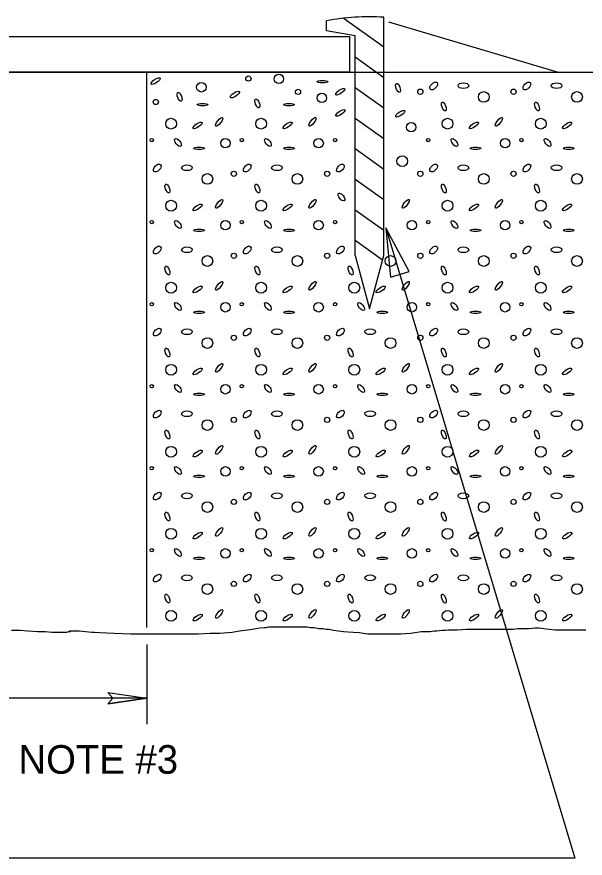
# Model space of a CAD drawing. Extents: x 12.5 to 19.6, y 6 to 16.
# Drawn here: x 16.462 to 17.653, y 11.231 to 12.995 of the extents above; entities that cross this region are included whole.
import ezdxf

# ---------------------------------------------------------------- set-up
doc = ezdxf.new("R2010")
doc.units = 0
for name, color, linetype in [('Default', 7, 'Continuous'), ('DETL-DIMS', 7, 'Continuous'), ('DETL-NOTE', 7, 'Continuous'), ('PVMT-FILL', 7, 'Continuous'), ('ROAD-EDGE', 7, 'Continuous'), ('SECT-SUBP_P', 7, 'Continuous')]:
    doc.layers.add(name, color=color, linetype=linetype)

msp = doc.modelspace()

# ---------------------------------------------------------------- linework, layer by layer
at = {"layer": 'Default'}
for p, q in [((17.1109, 12.9663), (17.1109, 12.9867)), ((17.2309, 12.9314), (17.1462, 12.9919)), ((17.2309, 12.4949), (17.2309, 12.994)), ((17.2409, 12.9844), (17.5967, 12.8792)), ((17.1109, 12.9663), (17.1709, 12.9557)), ((17.1709, 12.4949), (17.1709, 12.9557)), ((17.2309, 12.8673), (17.1709, 12.9102)), ((17.2309, 12.8033), (17.1709, 12.8461)), ((17.2309, 12.7392), (17.1709, 12.7821)), ((17.2309, 12.6752), (17.1709, 12.718)), ((17.2309, 12.6111), (17.1709, 12.654)), ((17.2309, 12.547), (17.1709, 12.5899)), ((17.2282, 12.4849), (17.1709, 12.5259)), ((17.1709, 12.4949), (17.2009, 12.3829)), ((17.2009, 12.3829), (17.2309, 12.4949))]:
    msp.add_line(p, q, dxfattribs=at)
msp.add_arc((17.2009, 12.4949), 0.5, 86.5602, 100.3698, dxfattribs=at)
at = {"layer": 'DETL-DIMS'}
for p, q in [((16.653, 11.5784), (16.7348, 11.5665)), ((16.653, 11.5784), (16.6632, 11.5665)), ((16.7348, 11.5665), (15.0348, 11.5665)), ((16.653, 11.5546), (16.7348, 11.5665)), ((16.653, 11.5546), (16.6632, 11.5665))]:
    msp.add_line(p, q, dxfattribs=at)
msp.add_lwpolyline([(17.2355, 12.5529), (17.6317, 11.2314), (16.1411, 11.2314)], dxfattribs=at)
for points in [[(17.2843, 12.4611), (17.2355, 12.5529), (17.2452, 12.4493)], [(16.653, 11.5784), (16.7348, 11.5665), (16.653, 11.5546), (16.6632, 11.5665)]]:
    msp.add_lwpolyline(points, close=True, dxfattribs=at)
at = {"layer": 'PVMT-FILL'}
for points in [[(16.4509, 11.7091), (16.463, 11.7091), (16.469, 11.7091), (16.4848, 11.7079), (16.5053, 11.7067), (16.5223, 11.7067), (16.5356, 11.7055), (16.5416, 11.7055), (16.5477, 11.7055), (16.5501, 11.7055), (16.5525, 11.7055), (16.5549, 11.7055), (16.5561, 11.7055), (16.5586, 11.7055), (16.5646, 11.7055), (16.567, 11.7055), (16.5707, 11.7067), (16.5719, 11.7067), (16.5731, 11.7067), (16.5743, 11.7067), (16.5731, 11.7067), (16.5719, 11.7067), (16.5731, 11.7079), (16.5743, 11.7079), (16.5755, 11.7079), (16.5767, 11.7079), (16.5791, 11.7079), (16.5924, 11.7079), (16.619, 11.7055), (16.6251, 11.7055), (16.636, 11.7043), (16.6662, 11.7031), (16.7001, 11.7018), (16.7231, 11.7018), (16.7533, 11.7018), (16.7836, 11.7018), (16.8198, 11.7018), (16.8307, 11.7018), (16.8428, 11.7018), (16.867, 11.7031), (16.8876, 11.7031), (16.9045, 11.7043), (16.913, 11.7055), (16.9287, 11.7079), (16.9456, 11.7103), (16.9553, 11.7115), (16.9626, 11.7127), (16.971, 11.7139), (16.9807, 11.7152), (16.9844, 11.7152), (16.9892, 11.7164), (16.9952, 11.7164), (17.0049, 11.7164), (17.0085, 11.7164), (17.0134, 11.7164), (17.0219, 11.7164), (17.0255, 11.7164), (17.0327, 11.7164), (17.0424, 11.7164), (17.0594, 11.7164), (17.0702, 11.7164), (17.0775, 11.7152), (17.0848, 11.7152), (17.0956, 11.7127), (17.1041, 11.7127), (17.1102, 11.7115), (17.1162, 11.7115), (17.1259, 11.7091), (17.1464, 11.7067), (17.167, 11.7055), (17.1803, 11.7043), (17.1876, 11.7031), (17.1973, 11.7018), (17.2057, 11.7018), (17.219, 11.7018), (17.2287, 11.7018), (17.2481, 11.7018), (17.2662, 11.7018), (17.2868, 11.7031), (17.3097, 11.7067), (17.3182, 11.7067), (17.3279, 11.7067), (17.3364, 11.7079), (17.3424, 11.7079), (17.3533, 11.7091), (17.3593, 11.7091), (17.3666, 11.7103), (17.3775, 11.7103), (17.3847, 11.7103), (17.4041, 11.7115), (17.4235, 11.7115), (17.4295, 11.7115), (17.4368, 11.7115), (17.4428, 11.7115), (17.4489, 11.7115), (17.4525, 11.7115), (17.4537, 11.7115), (17.4561, 11.7115), (17.4573, 11.7115), (17.4622, 11.7115), (17.467, 11.7115), (17.4718, 11.7115), (17.4791, 11.7115), (17.4827, 11.7115), (17.4851, 11.7115), (17.4876, 11.7115), (17.4948, 11.7115), (17.5021, 11.7115), (17.5118, 11.7127), (17.5275, 11.7127), (17.536, 11.7127), (17.5481, 11.7139), (17.5529, 11.7139)], [(17.5529, 11.7139), (17.5565, 11.7139), (17.5662, 11.7127), (17.5904, 11.7103), (17.617, 11.7103), (17.6291, 11.7103), (17.6388, 11.7103), (17.6545, 11.7103)]]:
    msp.add_lwpolyline(points, dxfattribs=at)
for centre, radius in [((17.0112, 12.8648), 0.0099), ((16.8487, 12.8472), 0.0099), ((16.9473, 12.8656), 0.00546), ((17.0513, 12.8375), 0.00546), ((17.3076, 12.8379), 0.00546), ((17.4405, 12.827), 0.0112), ((17.5029, 12.8379), 0.00546), ((17.6359, 12.827), 0.0112), ((16.7532, 12.8165), 0.00546), ((17.1013, 12.825), 0.0099), ((16.7853, 12.7709), 0.0113), ((16.9739, 12.7709), 0.0113), ((17.2886, 12.7634), 0.0099), ((17.3646, 12.7709), 0.0113), ((17.5599, 12.7709), 0.0113), ((16.7449, 12.7365), 0.00349), ((16.8992, 12.7299), 0.0099), ((16.9334, 12.7365), 0.00349), ((17.0945, 12.7299), 0.0099), ((17.1288, 12.7365), 0.00349), ((17.3241, 12.7365), 0.00349), ((17.4852, 12.7299), 0.0099), ((17.5194, 12.7365), 0.00349), ((17.2697, 12.6924), 0.0113), ((16.8613, 12.6551), 0.0112), ((16.9169, 12.666), 0.00546), ((17.0499, 12.6551), 0.0112), ((17.1123, 12.666), 0.00546), ((17.3076, 12.666), 0.00546), ((17.4405, 12.6551), 0.0112), ((17.5029, 12.666), 0.00546), ((17.6359, 12.6551), 0.0112), ((16.7853, 12.599), 0.0113), ((16.9739, 12.599), 0.0113), ((17.3646, 12.599), 0.0113), ((17.5599, 12.599), 0.0113), ((16.7449, 12.5646), 0.00349), ((16.8992, 12.558), 0.0099), ((16.9334, 12.5646), 0.00349), ((17.0945, 12.558), 0.0099), ((17.1288, 12.5646), 0.00349), ((17.2898, 12.558), 0.0099), ((17.3241, 12.5646), 0.00349), ((17.4852, 12.558), 0.0099), ((17.5194, 12.5646), 0.00349), ((16.8613, 12.4831), 0.0112), ((16.9169, 12.4941), 0.00546), ((17.0499, 12.4831), 0.0112), ((17.1123, 12.4941), 0.00546), ((17.2452, 12.4831), 0.0112), ((17.3076, 12.4941), 0.00546), ((17.4405, 12.4831), 0.0112), ((17.5029, 12.4941), 0.00546), ((17.6359, 12.4831), 0.0112), ((16.7853, 12.4271), 0.0113), ((16.9739, 12.4271), 0.0113), ((17.1692, 12.4271), 0.0113), ((17.3646, 12.4271), 0.0113), ((17.5599, 12.4271), 0.0113), ((16.7449, 12.3926), 0.00349), ((16.8992, 12.3861), 0.0099), ((16.9334, 12.3926), 0.00349), ((17.0945, 12.3861), 0.0099), ((17.1288, 12.3926), 0.00349), ((17.2898, 12.3861), 0.0099), ((17.3241, 12.3926), 0.00349), ((17.4852, 12.3861), 0.0099), ((17.5194, 12.3926), 0.00349), ((16.9169, 12.3221), 0.00546), ((17.1123, 12.3221), 0.00546), ((17.3076, 12.3221), 0.00546), ((17.5029, 12.3221), 0.00546), ((16.8613, 12.3112), 0.0112), ((17.0499, 12.3112), 0.0112), ((17.2452, 12.3112), 0.0112), ((17.4405, 12.3112), 0.0112), ((17.6359, 12.3112), 0.0112), ((16.7853, 12.2552), 0.0113), ((16.9739, 12.2552), 0.0113), ((17.1692, 12.2552), 0.0113), ((17.3646, 12.2552), 0.0113), ((17.5599, 12.2552), 0.0113), ((16.7449, 12.2207), 0.00349), ((16.8992, 12.2142), 0.0099), ((16.9334, 12.2207), 0.00349), ((17.0945, 12.2142), 0.0099), ((17.1288, 12.2207), 0.00349), ((17.2898, 12.2142), 0.0099), ((17.3241, 12.2207), 0.00349), ((17.4852, 12.2142), 0.0099), ((17.5194, 12.2207), 0.00349), ((16.8613, 12.1393), 0.0112), ((16.9169, 12.1502), 0.00546), ((17.0499, 12.1393), 0.0112), ((17.1123, 12.1502), 0.00546), ((17.2452, 12.1393), 0.0112), ((17.3076, 12.1502), 0.00546), ((17.4405, 12.1393), 0.0112), ((17.5029, 12.1502), 0.00546), ((17.6359, 12.1393), 0.0112), ((16.7853, 12.0833), 0.0113), ((16.9739, 12.0833), 0.0113), ((17.1692, 12.0833), 0.0113), ((17.3646, 12.0833), 0.0113), ((17.5599, 12.0833), 0.0113), ((16.7449, 12.0488), 0.00349), ((16.8992, 12.0422), 0.0099), ((16.9334, 12.0488), 0.00349), ((17.0945, 12.0422), 0.0099), ((17.1288, 12.0488), 0.00349), ((17.2898, 12.0422), 0.0099), ((17.3241, 12.0488), 0.00349), ((17.4852, 12.0422), 0.0099), ((17.5194, 12.0488), 0.00349), ((16.8613, 11.9674), 0.0112), ((16.9169, 11.9783), 0.00546), ((17.0499, 11.9674), 0.0112), ((17.1123, 11.9783), 0.00546), ((17.2452, 11.9674), 0.0112), ((17.3076, 11.9783), 0.00546), ((17.4405, 11.9674), 0.0112), ((17.5029, 11.9783), 0.00546), ((17.6359, 11.9674), 0.0112), ((16.7853, 11.9114), 0.0113), ((16.9739, 11.9114), 0.0113), ((17.1692, 11.9114), 0.0113), ((17.3646, 11.9114), 0.0113), ((17.5599, 11.9114), 0.0113), ((16.7449, 11.8769), 0.00349), ((16.8992, 11.8703), 0.0099), ((16.9334, 11.8769), 0.00349), ((17.0945, 11.8703), 0.0099), ((17.1288, 11.8769), 0.00349), ((17.2898, 11.8703), 0.0099), ((17.3241, 11.8769), 0.00349), ((17.4852, 11.8703), 0.0099), ((17.5194, 11.8769), 0.00349), ((16.8613, 11.7955), 0.0112), ((16.9169, 11.8064), 0.00546), ((17.0499, 11.7955), 0.0112), ((17.1123, 11.8064), 0.00546), ((17.2452, 11.7955), 0.0112), ((17.3076, 11.8064), 0.00546), ((17.4405, 11.7955), 0.0112), ((17.5029, 11.8064), 0.00546), ((17.6359, 11.7955), 0.0112), ((16.7853, 11.7394), 0.0113), ((16.9739, 11.7394), 0.0113), ((17.1692, 11.7394), 0.0113), ((17.3646, 11.7394), 0.0113), ((17.5599, 11.7394), 0.0113)]:
    msp.add_circle(centre, radius, dxfattribs=at)
for centre, major_axis, ratio in [((16.7529, 12.8601), (-0.00937, -0.00627), 0.338582), ((17.1024, 12.8589), (-0.0112, 0), 0.226521), ((17.2608, 12.8459), (-0.00349, 0.00926), 0.407015), ((17.3356, 12.8499), (0.007, 0.007), 0.581564), ((17.3978, 12.8506), (-0.0112, 0), 0.539468), ((17.5309, 12.8499), (0.007, 0.007), 0.581564), ((17.5931, 12.8506), (-0.0112, 0), 0.539468), ((16.9189, 12.832), (-0.00937, -0.00627), 0.338582), ((17.1398, 12.8379), (-0.00937, -0.00627), 0.338582), ((16.8031, 12.8273), (-0.00349, 0.00926), 0.407015), ((16.9661, 12.8133), (-0.00349, 0.00926), 0.407015), ((16.8511, 12.811), (-0.0112, 0), 0.226521), ((17.0325, 12.811), (-0.0112, 0), 0.226521), ((17.3568, 12.8069), (-0.00349, 0.00926), 0.407015), ((17.5521, 12.8069), (-0.00349, 0.00926), 0.407015), ((16.8862, 12.7749), (0.00695, 0.00888), 0.334091), ((17.0815, 12.7749), (0.00695, 0.00888), 0.334091), ((17.1398, 12.7934), (-0.00937, -0.00627), 0.338582), ((17.2654, 12.7917), (-0.00937, -0.00627), 0.338582), ((17.4722, 12.7749), (0.00695, 0.00888), 0.334091), ((16.8408, 12.7673), (-0.00937, -0.00627), 0.338582), ((17.0294, 12.7673), (-0.00937, -0.00627), 0.338582), ((17.42, 12.7673), (-0.00937, -0.00627), 0.338582), ((17.6153, 12.7673), (-0.00937, -0.00627), 0.338582), ((16.7997, 12.7315), (0.00613, -0.00777), 0.467307), ((16.9883, 12.7315), (0.00613, -0.00777), 0.467307), ((17.379, 12.7315), (0.00613, -0.00777), 0.467307), ((17.5743, 12.7315), (0.00613, -0.00777), 0.467307), ((16.844, 12.7195), (-0.0112, 0), 0.226521), ((17.0325, 12.7195), (-0.0112, 0), 0.226521), ((17.4232, 12.7195), (-0.0112, 0), 0.226521), ((17.6185, 12.7195), (-0.0112, 0), 0.226521), ((16.7563, 12.678), (0.007, 0.007), 0.581564), ((16.8185, 12.6786), (-0.0112, 0), 0.539468), ((16.9449, 12.678), (0.007, 0.007), 0.581564), ((17.0071, 12.6786), (-0.0112, 0), 0.539468), ((17.1402, 12.678), (0.007, 0.007), 0.581564), ((17.3356, 12.678), (0.007, 0.007), 0.581564), ((17.3978, 12.6786), (-0.0112, 0), 0.539468), ((17.5309, 12.678), (0.007, 0.007), 0.581564), ((17.5931, 12.6786), (-0.0112, 0), 0.539468), ((16.7775, 12.635), (-0.00349, 0.00926), 0.407015), ((16.9661, 12.635), (-0.00349, 0.00926), 0.407015), ((17.3568, 12.635), (-0.00349, 0.00926), 0.407015), ((17.5521, 12.635), (-0.00349, 0.00926), 0.407015), ((17.1422, 12.6172), (0.00613, -0.00777), 0.467307), ((16.8862, 12.603), (0.00695, 0.00888), 0.334091), ((17.0815, 12.603), (0.00695, 0.00888), 0.334091), ((17.2769, 12.603), (0.00695, 0.00888), 0.334091), ((17.4722, 12.603), (0.00695, 0.00888), 0.334091), ((16.8408, 12.5954), (-0.00937, -0.00627), 0.338582), ((17.0294, 12.5954), (-0.00937, -0.00627), 0.338582), ((17.42, 12.5954), (-0.00937, -0.00627), 0.338582), ((17.6153, 12.5954), (-0.00937, -0.00627), 0.338582), ((16.7997, 12.5596), (0.00613, -0.00777), 0.467307), ((16.9883, 12.5596), (0.00613, -0.00777), 0.467307), ((17.379, 12.5596), (0.00613, -0.00777), 0.467307), ((17.5743, 12.5596), (0.00613, -0.00777), 0.467307), ((16.844, 12.5476), (-0.0112, 0), 0.226521), ((17.0325, 12.5476), (-0.0112, 0), 0.226521), ((17.4232, 12.5476), (-0.0112, 0), 0.226521), ((17.6185, 12.5476), (-0.0112, 0), 0.226521), ((16.7563, 12.5061), (0.007, 0.007), 0.581564), ((16.8185, 12.5067), (-0.0112, 0), 0.539468), ((16.9449, 12.5061), (0.007, 0.007), 0.581564), ((17.0071, 12.5067), (-0.0112, 0), 0.539468), ((17.1402, 12.5061), (0.007, 0.007), 0.581564), ((17.3356, 12.5061), (0.007, 0.007), 0.581564), ((17.3978, 12.5067), (-0.0112, 0), 0.539468), ((17.5309, 12.5061), (0.007, 0.007), 0.581564), ((17.5931, 12.5067), (-0.0112, 0), 0.539468), ((16.7775, 12.4631), (-0.00349, 0.00926), 0.407015), ((16.9661, 12.4631), (-0.00349, 0.00926), 0.407015), ((17.1614, 12.4631), (-0.00349, 0.00926), 0.407015), ((17.3568, 12.4631), (-0.00349, 0.00926), 0.407015), ((17.5521, 12.4631), (-0.00349, 0.00926), 0.407015), ((16.8862, 12.4311), (0.00695, 0.00888), 0.334091), ((17.0815, 12.4311), (0.00695, 0.00888), 0.334091), ((17.2769, 12.4311), (0.00695, 0.00888), 0.334091), ((17.4722, 12.4311), (0.00695, 0.00888), 0.334091), ((16.8408, 12.4235), (-0.00937, -0.00627), 0.338582), ((17.0294, 12.4235), (-0.00937, -0.00627), 0.338582), ((17.2247, 12.4235), (-0.00937, -0.00627), 0.338582), ((17.42, 12.4235), (-0.00937, -0.00627), 0.338582), ((17.6153, 12.4235), (-0.00937, -0.00627), 0.338582), ((16.7997, 12.3876), (0.00613, -0.00777), 0.467307), ((16.9883, 12.3876), (0.00613, -0.00777), 0.467307), ((17.1836, 12.3876), (0.00613, -0.00777), 0.467307), ((17.379, 12.3876), (0.00613, -0.00777), 0.467307), ((17.5743, 12.3876), (0.00613, -0.00777), 0.467307), ((16.844, 12.3757), (-0.0112, 0), 0.226521), ((17.0325, 12.3757), (-0.0112, 0), 0.226521), ((17.2279, 12.3757), (-0.0112, 0), 0.226521), ((17.4232, 12.3757), (-0.0112, 0), 0.226521), ((17.6185, 12.3757), (-0.0112, 0), 0.226521), ((16.7563, 12.3341), (0.007, 0.007), 0.581564), ((16.8185, 12.3348), (-0.0112, 0), 0.539468), ((16.9449, 12.3341), (0.007, 0.007), 0.581564), ((17.0071, 12.3348), (-0.0112, 0), 0.539468), ((17.1402, 12.3341), (0.007, 0.007), 0.581564), ((17.2024, 12.3348), (-0.0112, 0), 0.539468), ((17.3356, 12.3341), (0.007, 0.007), 0.581564), ((17.3978, 12.3348), (-0.0112, 0), 0.539468), ((17.5309, 12.3341), (0.007, 0.007), 0.581564), ((17.5931, 12.3348), (-0.0112, 0), 0.539468), ((16.7775, 12.2912), (-0.00349, 0.00926), 0.407015), ((16.9661, 12.2912), (-0.00349, 0.00926), 0.407015), ((17.1614, 12.2912), (-0.00349, 0.00926), 0.407015), ((17.3568, 12.2912), (-0.00349, 0.00926), 0.407015), ((17.5521, 12.2912), (-0.00349, 0.00926), 0.407015), ((16.8408, 12.2516), (-0.00937, -0.00627), 0.338582), ((16.8862, 12.2592), (0.00695, 0.00888), 0.334091), ((17.0294, 12.2516), (-0.00937, -0.00627), 0.338582), ((17.0815, 12.2592), (0.00695, 0.00888), 0.334091), ((17.2247, 12.2516), (-0.00937, -0.00627), 0.338582), ((17.2769, 12.2592), (0.00695, 0.00888), 0.334091), ((17.42, 12.2516), (-0.00937, -0.00627), 0.338582), ((17.4722, 12.2592), (0.00695, 0.00888), 0.334091), ((17.6153, 12.2516), (-0.00937, -0.00627), 0.338582), ((16.7997, 12.2157), (0.00613, -0.00777), 0.467307), ((16.9883, 12.2157), (0.00613, -0.00777), 0.467307), ((17.1836, 12.2157), (0.00613, -0.00777), 0.467307), ((17.379, 12.2157), (0.00613, -0.00777), 0.467307), ((17.5743, 12.2157), (0.00613, -0.00777), 0.467307), ((16.844, 12.2038), (-0.0112, 0), 0.226521), ((17.0325, 12.2038), (-0.0112, 0), 0.226521), ((17.2279, 12.2038), (-0.0112, 0), 0.226521), ((17.4232, 12.2038), (-0.0112, 0), 0.226521), ((17.6185, 12.2038), (-0.0112, 0), 0.226521), ((16.7563, 12.1622), (0.007, 0.007), 0.581564), ((16.8185, 12.1629), (-0.0112, 0), 0.539468), ((16.9449, 12.1622), (0.007, 0.007), 0.581564), ((17.0071, 12.1629), (-0.0112, 0), 0.539468), ((17.1402, 12.1622), (0.007, 0.007), 0.581564), ((17.2024, 12.1629), (-0.0112, 0), 0.539468), ((17.3356, 12.1622), (0.007, 0.007), 0.581564), ((17.3978, 12.1629), (-0.0112, 0), 0.539468), ((17.5309, 12.1622), (0.007, 0.007), 0.581564), ((17.5931, 12.1629), (-0.0112, 0), 0.539468), ((16.7775, 12.1193), (-0.00349, 0.00926), 0.407015), ((16.9661, 12.1193), (-0.00349, 0.00926), 0.407015), ((17.1614, 12.1193), (-0.00349, 0.00926), 0.407015), ((17.3568, 12.1193), (-0.00349, 0.00926), 0.407015), ((17.5521, 12.1193), (-0.00349, 0.00926), 0.407015), ((16.8862, 12.0872), (0.00695, 0.00888), 0.334091), ((17.0815, 12.0872), (0.00695, 0.00888), 0.334091), ((17.2769, 12.0872), (0.00695, 0.00888), 0.334091), ((17.4722, 12.0872), (0.00695, 0.00888), 0.334091), ((16.8408, 12.0796), (-0.00937, -0.00627), 0.338582), ((17.0294, 12.0796), (-0.00937, -0.00627), 0.338582), ((17.2247, 12.0796), (-0.00937, -0.00627), 0.338582), ((17.42, 12.0796), (-0.00937, -0.00627), 0.338582), ((17.6153, 12.0796), (-0.00937, -0.00627), 0.338582), ((16.7997, 12.0438), (0.00613, -0.00777), 0.467307), ((16.9883, 12.0438), (0.00613, -0.00777), 0.467307), ((17.1836, 12.0438), (0.00613, -0.00777), 0.467307), ((17.379, 12.0438), (0.00613, -0.00777), 0.467307), ((17.5743, 12.0438), (0.00613, -0.00777), 0.467307), ((16.844, 12.0319), (-0.0112, 0), 0.226521), ((17.0325, 12.0319), (-0.0112, 0), 0.226521), ((17.2279, 12.0319), (-0.0112, 0), 0.226521), ((17.4232, 12.0319), (-0.0112, 0), 0.226521), ((17.6185, 12.0319), (-0.0112, 0), 0.226521), ((16.7563, 11.9903), (0.007, 0.007), 0.581564), ((16.8185, 11.991), (-0.0112, 0), 0.539468), ((16.9449, 11.9903), (0.007, 0.007), 0.581564), ((17.0071, 11.991), (-0.0112, 0), 0.539468), ((17.1402, 11.9903), (0.007, 0.007), 0.581564), ((17.2024, 11.991), (-0.0112, 0), 0.539468), ((17.3356, 11.9903), (0.007, 0.007), 0.581564), ((17.3978, 11.991), (-0.0112, 0), 0.539468), ((17.5309, 11.9903), (0.007, 0.007), 0.581564), ((17.5931, 11.991), (-0.0112, 0), 0.539468), ((16.7775, 11.9474), (-0.00349, 0.00926), 0.407015), ((16.9661, 11.9474), (-0.00349, 0.00926), 0.407015), ((17.1614, 11.9474), (-0.00349, 0.00926), 0.407015), ((17.3568, 11.9474), (-0.00349, 0.00926), 0.407015), ((17.5521, 11.9474), (-0.00349, 0.00926), 0.407015), ((16.8862, 11.9153), (0.00695, 0.00888), 0.334091), ((17.0815, 11.9153), (0.00695, 0.00888), 0.334091), ((17.2769, 11.9153), (0.00695, 0.00888), 0.334091), ((17.4722, 11.9153), (0.00695, 0.00888), 0.334091), ((16.8408, 11.9077), (-0.00937, -0.00627), 0.338582), ((17.0294, 11.9077), (-0.00937, -0.00627), 0.338582), ((17.2247, 11.9077), (-0.00937, -0.00627), 0.338582), ((17.42, 11.9077), (-0.00937, -0.00627), 0.338582), ((17.6153, 11.9077), (-0.00937, -0.00627), 0.338582), ((16.7997, 11.8719), (0.00613, -0.00777), 0.467307), ((16.9883, 11.8719), (0.00613, -0.00777), 0.467307), ((17.1836, 11.8719), (0.00613, -0.00777), 0.467307), ((17.379, 11.8719), (0.00613, -0.00777), 0.467307), ((17.5743, 11.8719), (0.00613, -0.00777), 0.467307), ((16.844, 11.86), (-0.0112, 0), 0.226521), ((17.0325, 11.86), (-0.0112, 0), 0.226521), ((17.2279, 11.86), (-0.0112, 0), 0.226521), ((17.4232, 11.86), (-0.0112, 0), 0.226521), ((17.6185, 11.86), (-0.0112, 0), 0.226521), ((16.7563, 11.8184), (0.007, 0.007), 0.581564), ((16.8185, 11.8191), (-0.0112, 0), 0.539468), ((16.9449, 11.8184), (0.007, 0.007), 0.581564), ((17.0071, 11.8191), (-0.0112, 0), 0.539468), ((17.1402, 11.8184), (0.007, 0.007), 0.581564), ((17.2024, 11.8191), (-0.0112, 0), 0.539468), ((17.3356, 11.8184), (0.007, 0.007), 0.581564), ((17.3978, 11.8191), (-0.0112, 0), 0.539468), ((17.5309, 11.8184), (0.007, 0.007), 0.581564), ((17.5931, 11.8191), (-0.0112, 0), 0.539468), ((16.7775, 11.7754), (-0.00349, 0.00926), 0.407015), ((16.9661, 11.7754), (-0.00349, 0.00926), 0.407015), ((17.1614, 11.7754), (-0.00349, 0.00926), 0.407015), ((17.3568, 11.7754), (-0.00349, 0.00926), 0.407015), ((17.5521, 11.7754), (-0.00349, 0.00926), 0.407015), ((16.8862, 11.7434), (0.00695, 0.00888), 0.334091), ((17.0815, 11.7434), (0.00695, 0.00888), 0.334091), ((17.2769, 11.7434), (0.00695, 0.00888), 0.334091), ((17.4722, 11.7434), (0.00695, 0.00888), 0.334091), ((16.8408, 11.7358), (-0.00937, -0.00627), 0.338582), ((17.0294, 11.7358), (-0.00937, -0.00627), 0.338582), ((17.2247, 11.7358), (-0.00937, -0.00627), 0.338582), ((17.42, 11.7358), (-0.00937, -0.00627), 0.338582), ((17.6153, 11.7358), (-0.00937, -0.00627), 0.338582)]:
    msp.add_ellipse(centre, major_axis=major_axis, ratio=ratio, dxfattribs=at)
at = {"layer": 'ROAD-EDGE'}
for p, q in [((13.3339, 12.8792), (18.4339, 12.8792)), ((16.7339, 12.8792), (16.7339, 11.7146)), ((16.7346, 11.6791), (16.7346, 11.5126))]:
    msp.add_line(p, q, dxfattribs=at)
at = {"layer": 'SECT-SUBP_P'}
msp.add_lwpolyline([(14.6089, 12.9536), (17.1589, 12.9536), (17.1589, 12.8792), (14.6089, 12.8792)], close=True, dxfattribs=at)

# ---------------------------------------------------------------- texts
at = {"layer": 'DETL-NOTE'}
msp.add_text('SEE NOTE #3', height=0.06, dxfattribs=at).set_placement((16.2827, 11.4084))

doc.saveas('drawing.dxf')
